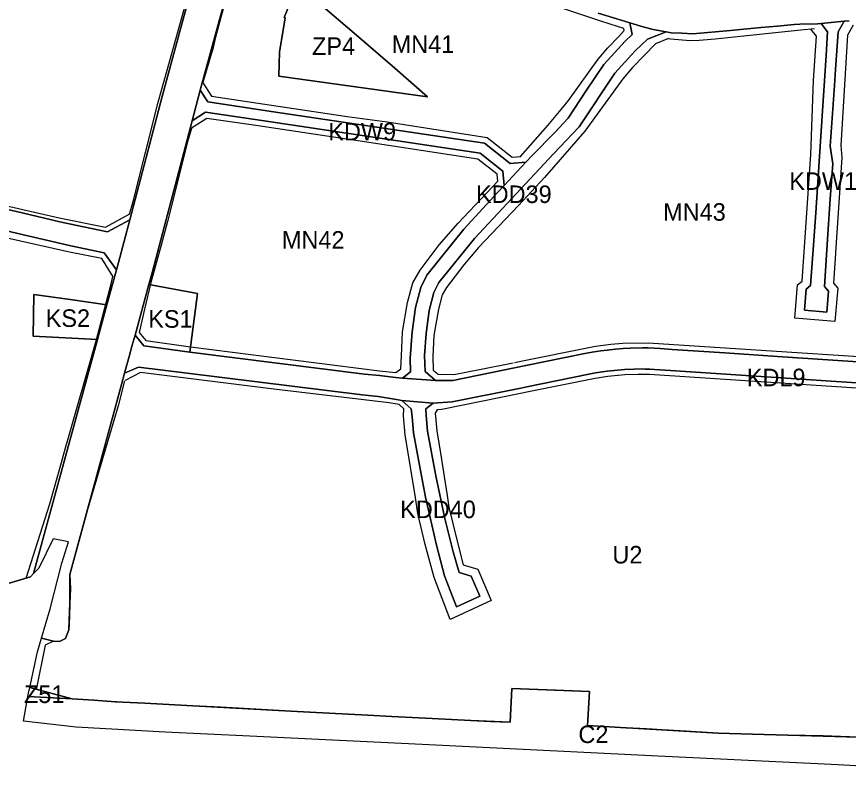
# Model space of a CAD drawing. Extents: x 7428841 to 7433518, y 5545054 to 5546840.
# Drawn here: x 7431482.5 to 7431956.4, y 5545131.2 to 5545561 of the extents above; entities that cross this region are included whole.
import ezdxf

# ---------------------------------------------------------------- set-up
doc = ezdxf.new("R2010")
doc.units = 0
for name, color, linetype in [('linie_rozgraniczajace', 7, 'Continuous'), ('linie_zabudowy_nieprzekraczalne', 7, 'Continuous'), ('oznaczenia_przeznaczen', 7, 'Continuous')]:
    doc.layers.add(name, color=color, linetype=linetype)

msp = doc.modelspace()

# ---------------------------------------------------------------- linework, layer by layer
at = {"layer": 'linie_rozgraniczajace'}
for points in [[(7431631.82, 5545527.07), (7431632.3, 5545540.87), (7431635.52, 5545560.38), (7431634.96, 5545560.58), (7431642.48, 5545579.21), (7431652.8, 5545570.54), (7431695.08, 5545623.19), (7431696.97, 5545622.15), (7431654.26, 5545569.14), (7431676.12, 5545550.46), (7431697.97, 5545531.78), (7431716.53, 5545515.45)], [(7431702.34, 5545355.13), (7431706.91, 5545358.68), (7431706.77, 5545366.51), (7431707.76, 5545381.45), (7431709.64, 5545395.37), (7431712.71, 5545406.73), (7431716.15, 5545413.87), (7431737.28, 5545439.99), (7431756.72, 5545461), (7431760.3, 5545464.86), (7431772.58, 5545478.14), (7431776.17, 5545482.01), (7431789.16, 5545495.02), (7431796.72, 5545503.3), (7431806.88, 5545518.56), (7431817.04, 5545533.82), (7431829.2, 5545547.13), (7431833.25, 5545550.93), (7431831.78, 5545557.6), (7431840.04, 5545555.11), (7431845.2, 5545553.64), (7431852.53, 5545552.34), (7431841.94, 5545548.13), (7431834.91, 5545541.51), (7431823.36, 5545528.88), (7431803.04, 5545498.36), (7431788.44, 5545482.98), (7431743.33, 5545434.75), (7431722.96, 5545409.57), (7431720.24, 5545403.92), (7431717.5, 5545393.78), (7431715.72, 5545380.64), (7431714.88, 5545368.03), (7431715.23, 5545358.88), (7431721.17, 5545353.79)], [(7431931.29, 5545393.81), (7431932.25, 5545405.79), (7431934.84, 5545407.96), (7431936.28, 5545428.33), (7431937.77, 5545449.32), (7431939.88, 5545481.47), (7431940.83, 5545495.82), (7431941.77, 5545510.16), (7431942.72, 5545524.51), (7431943.66, 5545538.85), (7431944.53, 5545552.32), (7431940.82, 5545557.19), (7431954.01, 5545558.44), (7431950.5, 5545552.36), (7431949.1, 5545530.95), (7431948.49, 5545521.83), (7431945.99, 5545487.22), (7431947.47, 5545477.17), (7431946.1, 5545457.21), (7431944.74, 5545437.25), (7431942.84, 5545407.28), (7431945.12, 5545404.74), (7431944.08, 5545392.79)], [(7431582.47, 5545501.72), (7431584.78, 5545510.45), (7431587.12, 5545519.14), (7431591.38, 5545512.49), (7431628.75, 5545506.9), (7431749.07, 5545488.91), (7431763.71, 5545477.46), (7431772.58, 5545478.14), (7431760.3, 5545464.86), (7431759.58, 5545473.07), (7431746.6, 5545483.22), (7431623.55, 5545501.61), (7431590.11, 5545506.61)], [(7431557.82, 5545408.54), (7431559.81, 5545415.82), (7431582.47, 5545501.72), (7431590.11, 5545506.61), (7431623.55, 5545501.61), (7431746.6, 5545483.22), (7431759.58, 5545473.07), (7431760.3, 5545464.86), (7431756.72, 5545461), (7431737.28, 5545439.99), (7431716.15, 5545413.87), (7431712.71, 5545406.73), (7431709.64, 5545395.37), (7431707.76, 5545381.45), (7431706.77, 5545366.51), (7431706.91, 5545358.68), (7431702.34, 5545355.13), (7431698.36, 5545355.45), (7431689.19, 5545356.62), (7431680.63, 5545357.51), (7431581.23, 5545369.92), (7431585.56, 5545403.36)], [(7431549.93, 5545379.65), (7431557.82, 5545408.54), (7431585.56, 5545403.36), (7431581.23, 5545369.92), (7431581.2, 5545369.92), (7431555.01, 5545373.59)], [(7431491.94, 5545379.16), (7431492.17, 5545402.84), (7431513.05, 5545399.92), (7431533.94, 5545397), (7431528.52, 5545377.15)], [(7431701.88, 5545342.47), (7431719.83, 5545340.97), (7431715.7, 5545337.64), (7431715.85, 5545333.87), (7431716.56, 5545325.02), (7431721.24, 5545299.6), (7431726.5, 5545275.26), (7431731.19, 5545256.28), (7431734.6, 5545244.41), (7431741.53, 5545242.34), (7431746.36, 5545231.01), (7431733.12, 5545224.99), (7431726.34, 5545242.59), (7431721.62, 5545260.03), (7431715.42, 5545287.39), (7431711.36, 5545308.71), (7431708.62, 5545323.99), (7431707.86, 5545333.25), (7431707.31, 5545337.63)], [(7431488.86, 5545173.88), (7431489.19, 5545175.72), (7431489.91, 5545178.99), (7431514.11, 5545172.58)]]:
    msp.add_lwpolyline(points, close=True, dxfattribs=at)
for points in [[(7431610.21, 5545603.92), (7431596.09, 5545552.33), (7431587.12, 5545519.14), (7431584.78, 5545510.45), (7431582.47, 5545501.72), (7431559.81, 5545415.82), (7431557.82, 5545408.54), (7431549.93, 5545379.65), (7431548.38, 5545373.97), (7431546.62, 5545367.51), (7431544, 5545357.92), (7431542.28, 5545351.63), (7431512.74, 5545243.36), (7431512.8, 5545227.22), (7431512.28, 5545211.84), (7431510.24, 5545206.92), (7431506.97, 5545205.11), (7431503.5, 5545205.32), (7431496.68, 5545207.04), (7431501.62, 5545223.73), (7431508.24, 5545249.78), (7431512.11, 5545261.95), (7431503.26, 5545263.72), (7431495.12, 5545247.02), (7431492.14, 5545243.83)], [(7431813.84, 5545563.02), (7431826.94, 5545559.07), (7431831.78, 5545557.6), (7431833.25, 5545550.93), (7431829.2, 5545547.13), (7431817.04, 5545533.82), (7431806.88, 5545518.56), (7431796.72, 5545503.3), (7431789.16, 5545495.02), (7431776.17, 5545482.01), (7431772.58, 5545478.14), (7431763.71, 5545477.46), (7431749.07, 5545488.91), (7431628.75, 5545506.9), (7431591.38, 5545512.49), (7431587.12, 5545519.14), (7431596.09, 5545552.33), (7431610.21, 5545603.92)], [(7431588.14, 5545599.59), (7431565.45, 5545515.61), (7431546.89, 5545445.26), (7431534.28, 5545438.43), (7431515.98, 5545442.19), (7431507.03, 5545444.27), (7431485.58, 5545449.26), (7431455.18, 5545456.33)], [(7431492.14, 5545243.83), (7431528.52, 5545377.15), (7431533.94, 5545397), (7431539.34, 5545416.76), (7431540.49, 5545421.01), (7431546.89, 5545445.26), (7431565.45, 5545515.61), (7431588.14, 5545599.59)], [(7431642.48, 5545579.21), (7431634.96, 5545560.58), (7431635.52, 5545560.38), (7431632.3, 5545540.87), (7431631.82, 5545527.07), (7431716.53, 5545515.45), (7431697.97, 5545531.78), (7431676.12, 5545550.46), (7431654.26, 5545569.14)], [(7431956.9, 5545558.72), (7431954.01, 5545558.44), (7431940.82, 5545557.19), (7431939.04, 5545557.02), (7431928.71, 5545556.84), (7431925.54, 5545556.56), (7431916, 5545555.7), (7431906.55, 5545554.87), (7431889.17, 5545553.07), (7431867.69, 5545551.28), (7431861.54, 5545551.56), (7431855.39, 5545551.84), (7431852.53, 5545552.34), (7431845.2, 5545553.64), (7431840.04, 5545555.11), (7431831.78, 5545557.6), (7431826.94, 5545559.07), (7431813.84, 5545563.02)], [(7431976.25, 5545363.59), (7431916.07, 5545367.52), (7431885.98, 5545369.51), (7431855.89, 5545371.5), (7431849.1, 5545371.96), (7431842.28, 5545372.33), (7431839.15, 5545372.33), (7431832.27, 5545372.31), (7431827.97, 5545372.02), (7431823.66, 5545371.74), (7431818.89, 5545371.16), (7431815.27, 5545370.72), (7431810.35, 5545369.98), (7431806.17, 5545369.13), (7431772.65, 5545362.35), (7431731.09, 5545353.86), (7431721.17, 5545353.79), (7431715.23, 5545358.88), (7431714.88, 5545368.03), (7431715.72, 5545380.64), (7431717.5, 5545393.78), (7431720.24, 5545403.92), (7431722.96, 5545409.57), (7431743.33, 5545434.75), (7431788.44, 5545482.98), (7431803.04, 5545498.36), (7431823.36, 5545528.88), (7431834.91, 5545541.51), (7431841.94, 5545548.13), (7431852.53, 5545552.34), (7431855.39, 5545551.84), (7431861.54, 5545551.56), (7431867.69, 5545551.28), (7431889.17, 5545553.07), (7431906.55, 5545554.87), (7431916, 5545555.7), (7431925.54, 5545556.56), (7431928.71, 5545556.84), (7431939.04, 5545557.02), (7431940.82, 5545557.19), (7431944.53, 5545552.32), (7431943.66, 5545538.85), (7431942.72, 5545524.51), (7431941.77, 5545510.16), (7431940.83, 5545495.82), (7431939.88, 5545481.47), (7431937.77, 5545449.32), (7431936.28, 5545428.33), (7431934.84, 5545407.96), (7431932.25, 5545405.79), (7431931.29, 5545393.81), (7431944.08, 5545392.79), (7431945.12, 5545404.74), (7431942.84, 5545407.28), (7431944.74, 5545437.25), (7431946.1, 5545457.21), (7431947.47, 5545477.17), (7431945.99, 5545487.22), (7431948.49, 5545521.83), (7431949.1, 5545530.95), (7431950.5, 5545552.36), (7431954.01, 5545558.44), (7431956.9, 5545558.72)], [(7431455.18, 5545456.33), (7431485.58, 5545449.26), (7431507.03, 5545444.27), (7431515.98, 5545442.19), (7431534.28, 5545438.43), (7431546.89, 5545445.26), (7431540.49, 5545421.01), (7431539.34, 5545416.76), (7431532.4, 5545426.57), (7431513.41, 5545430.47), (7431483.24, 5545437.48), (7431453.07, 5545444.5)], [(7431453.07, 5545444.5), (7431483.24, 5545437.48), (7431513.41, 5545430.47), (7431532.4, 5545426.57), (7431539.34, 5545416.76), (7431533.94, 5545397), (7431513.05, 5545399.92), (7431492.17, 5545402.84), (7431491.94, 5545379.16), (7431528.52, 5545377.15), (7431492.14, 5545243.83), (7431490.36, 5545241.93), (7431408.52, 5545217.78)], [(7431989.5, 5545350.62), (7431915.28, 5545355.55), (7431855.06, 5545359.53), (7431845.92, 5545360.14), (7431843.25, 5545360.32), (7431840.57, 5545360.35), (7431838.8, 5545360.38), (7431834.19, 5545360.29), (7431828.73, 5545360.05), (7431818.95, 5545359.17), (7431812.27, 5545358.14), (7431808.55, 5545357.37), (7431773.14, 5545350.21), (7431769.68, 5545349.51), (7431730.65, 5545341.61), (7431719.83, 5545340.97), (7431701.88, 5545342.47), (7431697.71, 5545343.25), (7431688.4, 5545344.63), (7431679.32, 5545345.58), (7431579.71, 5545358.02), (7431551.95, 5545361.5), (7431544, 5545357.92), (7431546.62, 5545367.51), (7431548.38, 5545373.97), (7431549.93, 5545379.65), (7431555.01, 5545373.59), (7431581.2, 5545369.92), (7431581.23, 5545369.92), (7431680.63, 5545357.51), (7431689.19, 5545356.62), (7431698.36, 5545355.45), (7431702.34, 5545355.13), (7431721.17, 5545353.79), (7431731.09, 5545353.86), (7431772.65, 5545362.35), (7431806.17, 5545369.13), (7431810.35, 5545369.98), (7431815.27, 5545370.72), (7431818.89, 5545371.16), (7431823.66, 5545371.74), (7431827.97, 5545372.02), (7431832.27, 5545372.31), (7431839.15, 5545372.33), (7431842.28, 5545372.33), (7431849.1, 5545371.96), (7431855.89, 5545371.5), (7431885.98, 5545369.51), (7431916.07, 5545367.52), (7431976.25, 5545363.59)], [(7431489.91, 5545178.99), (7431494.37, 5545199.25), (7431496.68, 5545207.04), (7431503.5, 5545205.32), (7431506.97, 5545205.11), (7431510.24, 5545206.92), (7431512.28, 5545211.84), (7431512.8, 5545227.22), (7431512.74, 5545243.36), (7431542.28, 5545351.63), (7431544, 5545357.92), (7431551.95, 5545361.5), (7431579.71, 5545358.02), (7431679.32, 5545345.58), (7431688.4, 5545344.63), (7431697.71, 5545343.25), (7431701.88, 5545342.47), (7431707.31, 5545337.63), (7431707.86, 5545333.25), (7431708.62, 5545323.99), (7431711.36, 5545308.71), (7431715.42, 5545287.39), (7431721.62, 5545260.03), (7431726.34, 5545242.59), (7431733.12, 5545224.99), (7431746.36, 5545231.01), (7431741.53, 5545242.34), (7431734.6, 5545244.41), (7431731.19, 5545256.28), (7431726.5, 5545275.26), (7431721.24, 5545299.6), (7431716.56, 5545325.02), (7431715.85, 5545333.87), (7431715.7, 5545337.64), (7431719.83, 5545340.97), (7431730.65, 5545341.61), (7431769.68, 5545349.51), (7431773.14, 5545350.21), (7431808.55, 5545357.37), (7431812.27, 5545358.14), (7431818.95, 5545359.17), (7431828.73, 5545360.05), (7431834.19, 5545360.29), (7431838.8, 5545360.38), (7431840.57, 5545360.35), (7431843.25, 5545360.32), (7431845.92, 5545360.14), (7431855.06, 5545359.53), (7431915.28, 5545355.55), (7431989.5, 5545350.62)], [(7432016.49, 5545131.23), (7431950.63, 5545134.86), (7431848.04, 5545139.94), (7431713.61, 5545146.54), (7431615.37, 5545151.3), (7431567.17, 5545153.64), (7431516.4, 5545156.31), (7431486.31, 5545159.88), (7431488.86, 5545173.88), (7431514.11, 5545172.58), (7431526.49, 5545171.75), (7431538.87, 5545170.91), (7431555.57, 5545170.03), (7431582.84, 5545168.57), (7431598.79, 5545167.71), (7431638.61, 5545165.58), (7431649.6, 5545164.98), (7431682.57, 5545163.2), (7431695.99, 5545162.47), (7431711.89, 5545161.62), (7431741.3, 5545160.22), (7431763.58, 5545159.17), (7431764.56, 5545178.47), (7431789.52, 5545177.5), (7431808.88, 5545176.74), (7431807.66, 5545157.3), (7431829.68, 5545156.05), (7431841.33, 5545155.38), (7431850.2, 5545154.88), (7431860.62, 5545154.32), (7431882.24, 5545153.07), (7431888.64, 5545152.7), (7431901.68, 5545152.38), (7431921.81, 5545151.88), (7431942, 5545151.39), (7431962.01, 5545150.71)], [(7431526.49, 5545171.75), (7431514.11, 5545172.58), (7431489.91, 5545178.99)], [(7431962.01, 5545150.71), (7431942, 5545151.39), (7431921.81, 5545151.88), (7431901.68, 5545152.38), (7431888.64, 5545152.7), (7431882.24, 5545153.07), (7431860.62, 5545154.32), (7431850.2, 5545154.88), (7431841.33, 5545155.38), (7431829.68, 5545156.05), (7431807.66, 5545157.3), (7431808.88, 5545176.74), (7431789.52, 5545177.5), (7431764.56, 5545178.47), (7431763.58, 5545159.17), (7431741.3, 5545160.22), (7431711.89, 5545161.62), (7431695.99, 5545162.47), (7431682.57, 5545163.2), (7431649.6, 5545164.98), (7431638.61, 5545165.58), (7431598.79, 5545167.71), (7431582.84, 5545168.57), (7431555.57, 5545170.03), (7431538.87, 5545170.91), (7431526.49, 5545171.75)]]:
    msp.add_lwpolyline(points, dxfattribs=at)
at = {"layer": 'linie_zabudowy_nieprzekraczalne'}
for points in [[(7431546.82, 5545448.63), (7431548.84, 5545455.82), (7431563.04, 5545512.38), (7431568.23, 5545530.64), (7431592.88, 5545619.09), (7431599.29, 5545642.6), (7431607.98, 5545676.87), (7431610.19, 5545692.41), (7431612.33, 5545705.4), (7431615.98, 5545719.72)], [(7431637.5, 5545673.08), (7431634.97, 5545673), (7431632.44, 5545672.91), (7431628.79, 5545668.13), (7431627.99, 5545664.43), (7431621.49, 5545643.25), (7431616.1, 5545622.96), (7431606.17, 5545588.13), (7431604.49, 5545581.76), (7431597.75, 5545556.46), (7431595.63, 5545548.68), (7431594, 5545541.71), (7431593.96, 5545541.56), (7431588.47, 5545523.55)], [(7431828.41, 5545554.27), (7431824.82, 5545555.48), (7431815.24, 5545558.5), (7431787.92, 5545567.63), (7431780.54, 5545570.78), (7431772.29, 5545574.5), (7431764.26, 5545579), (7431750.25, 5545587.35), (7431729.4, 5545599.47), (7431708.37, 5545612.07), (7431695.18, 5545619.71)], [(7431959.13, 5545556.14), (7431955.84, 5545550.5), (7431952.13, 5545487.57), (7431952.72, 5545480.8), (7431947.87, 5545409.16), (7431950.28, 5545406.46), (7431948.64, 5545387.4), (7431925.91, 5545389.23), (7431927.43, 5545408.27), (7431930, 5545410.43), (7431935.05, 5545482.62), (7431936.47, 5545524.63), (7431938.22, 5545549.97), (7431934.91, 5545553.91)], [(7431769.59, 5545481.45), (7431785.14, 5545499.12), (7431791.79, 5545506.96), (7431796.85, 5545513.35), (7431813.75, 5545536.79), (7431819.27, 5545543.3), (7431825.54, 5545549.82), (7431828.68, 5545553.08), (7431828.41, 5545554.27)], [(7431937.02, 5545554.04), (7431929.38, 5545553.29), (7431895, 5545549.82), (7431880.53, 5545548.23), (7431871.3, 5545547.52), (7431866.08, 5545547.31), (7431855.13, 5545548.25), (7431853.6, 5545548.42)], [(7431853.98, 5545548.62), (7431846.57, 5545545.55), (7431833.43, 5545532.13), (7431827.92, 5545525.67), (7431806.19, 5545495.86), (7431783.16, 5545469.48), (7431768.41, 5545453.43), (7431745.54, 5545429.55), (7431737.19, 5545419.72), (7431727.35, 5545406.73), (7431724.96, 5545402.58), (7431722.81, 5545394.39), (7431720.21, 5545379.44), (7431719.67, 5545367.57), (7431719.72, 5545359.78)], [(7431588.46, 5545523.68), (7431593.48, 5545515.71), (7431670.71, 5545504.16), (7431693.66, 5545501.12), (7431750.5, 5545492.23), (7431764.8, 5545481.06), (7431769.72, 5545481.41)], [(7431756.59, 5545467.25), (7431756.22, 5545471.37), (7431745.18, 5545479.9), (7431678.24, 5545490.11), (7431618.75, 5545498.96), (7431590.89, 5545502.96), (7431582.03, 5545497.49)], [(7431582.01, 5545497.35), (7431579.86, 5545489.69), (7431568.43, 5545444.41), (7431564.76, 5545430.84), (7431558.89, 5545409.67), (7431555.34, 5545394.44), (7431552.23, 5545381.12)], [(7431770.09, 5545481.33), (7431770.09, 5545481.33)], [(7431701.43, 5545360.49), (7431701.67, 5545367.87), (7431702.35, 5545381.53), (7431705.21, 5545398.22), (7431708.16, 5545409.47), (7431712.31, 5545416.69), (7431723.15, 5545430.99), (7431734, 5545443.4), (7431756.59, 5545467.25)], [(7431437.1, 5545460.94), (7431439.95, 5545460.67), (7431460.09, 5545457.1), (7431506.73, 5545446.48), (7431533.09, 5545441.2), (7431546.9, 5545448.68)], [(7431537.38, 5545412.87), (7431531.04, 5545423.28), (7431512.6, 5545426.83), (7431456.52, 5545439.45), (7431437.32, 5545442.86), (7431423.17, 5545444.54), (7431415.26, 5545444.9), (7431398.17, 5545444.33), (7431384.65, 5545443.12), (7431373.07, 5545442.05), (7431347.57, 5545437.08), (7431322.03, 5545433.25), (7431296.58, 5545430.64)], [(7431527.72, 5545376.46), (7431536.26, 5545408.95), (7431537.37, 5545413)], [(7431552.23, 5545381.12), (7431556.16, 5545376.68), (7431581.58, 5545372.9), (7431689.29, 5545359.4), (7431698.44, 5545358.43)], [(7431510.93, 5545317.44), (7431527.71, 5545376.46)], [(7431772.52, 5545365.39), (7431805.61, 5545372.08), (7431812.34, 5545373.31), (7431820.95, 5545374.43), (7431827.8, 5545375.02), (7431842.35, 5545375.33), (7431886.18, 5545372.51), (7431956.49, 5545367.85), (7431996.97, 5545365.16)], [(7431731.59, 5545357.23), (7431747.16, 5545360.26), (7431765.37, 5545363.94)], [(7431766.09, 5545364.04), (7431772.52, 5545365.39)], [(7431700.42, 5545340.06), (7431694.74, 5545341.12), (7431629.07, 5545348.83), (7431552.99, 5545358.39), (7431544.35, 5545353.85)], [(7431698.44, 5545358.43), (7431701.43, 5545360.49)], [(7431719.72, 5545359.78), (7431722.57, 5545357.39), (7431731.59, 5545357.23)], [(7432123.94, 5545168.43), (7432129.29, 5545267.88), (7432131.88, 5545305.09), (7432124.1, 5545344.75), (7432119.78, 5545348.17), (7432080.99, 5545346.88), (7432073.28, 5545347.3), (7431995.59, 5545347.2), (7431915.08, 5545352.55), (7431843.14, 5545357.32), (7431836.54, 5545357.33), (7431828.92, 5545357.05), (7431819.33, 5545356.19), (7431810.9, 5545354.8)], [(7431543.94, 5545353.58), (7431540.28, 5545339.44), (7431522.94, 5545280.84), (7431512.74, 5545243.36), (7431513.07, 5545235.23), (7431512.8, 5545227.22), (7431512.53, 5545219.2), (7431512.28, 5545211.84), (7431510.24, 5545206.92), (7431506.97, 5545205.11), (7431503.5, 5545205.32), (7431498.69, 5545203), (7431493.57, 5545177.7)], [(7431811.2, 5545354.85), (7431773.26, 5545347.17)], [(7431773.26, 5545347.17), (7431770.55, 5545346.62)], [(7431770.55, 5545346.62), (7431724.83, 5545337.37), (7431722.08, 5545337.05)], [(7431703.02, 5545337.66), (7431700.42, 5545340.06)], [(7431722.08, 5545337.05), (7431720.86, 5545335.23), (7431721.8, 5545325.19), (7431723.97, 5545312.48), (7431727.75, 5545288.28), (7431728.79, 5545281.68), (7431733.29, 5545263.14), (7431736.98, 5545248.78), (7431745.21, 5545246.47), (7431752.87, 5545228.48), (7431729.56, 5545217.77), (7431720.46, 5545241.61), (7431715.22, 5545260.5), (7431711.12, 5545278.16), (7431709.67, 5545287.12), (7431703.93, 5545322.95), (7431702.91, 5545333.61), (7431703.02, 5545337.66)], [(7431487.91, 5545241.33), (7431501.46, 5545283.55), (7431508.09, 5545307.09), (7431510.95, 5545317.47)], [(7431371.02, 5545186.65), (7431381.38, 5545190.05), (7431382.17, 5545203.21), (7431390.7, 5545202.64), (7431392.17, 5545218.63), (7431408.52, 5545217.78), (7431449.44, 5545229.86), (7431469.9, 5545235.89), (7431490.36, 5545241.93)], [(7431514.11, 5545172.58), (7431532.68, 5545171.33), (7431569.2, 5545169.3), (7431638.61, 5545165.58), (7431752.44, 5545159.69), (7431763.58, 5545159.17), (7431764.56, 5545178.47), (7431808.88, 5545176.74), (7431807.66, 5545157.3), (7431882.24, 5545153.07), (7431962.01, 5545150.71), (7432046.18, 5545144.47), (7432058.55, 5545144.53), (7432070.92, 5545144.6), (7432090.47, 5545154.75), (7432091.35, 5545170.74), (7432123.82, 5545168.62)]]:
    msp.add_lwpolyline(points, dxfattribs=at)

# ---------------------------------------------------------------- texts
at = {"layer": 'oznaczenia_przeznaczen'}
for s, p in [('ZP4', (7431650.8, 5545539.26)), ('MN41', (7431696.17, 5545540.34)), ('KDW9', (7431660.03, 5545490.54)), ('KDW10', (7431922.7, 5545462.39)), ('KDD39', (7431744.22, 5545454.89)), ('MN43', (7431850.84, 5545444.81)), ('MN42', (7431633.61, 5545428.88)), ('KS2', (7431499.03, 5545384.34)), ('KS1', (7431557.46, 5545383.88)), ('KDL9', (7431898.52, 5545350.55)), ('KDD40', (7431701, 5545275.43)), ('U2', (7431821.92, 5545249.61)), ('Z51', (7431486.66, 5545170.15)), ('C2', (7431802.55, 5545147.34))]:
    msp.add_text(s, height=10, dxfattribs=at).set_placement(p)

doc.saveas('drawing.dxf')
